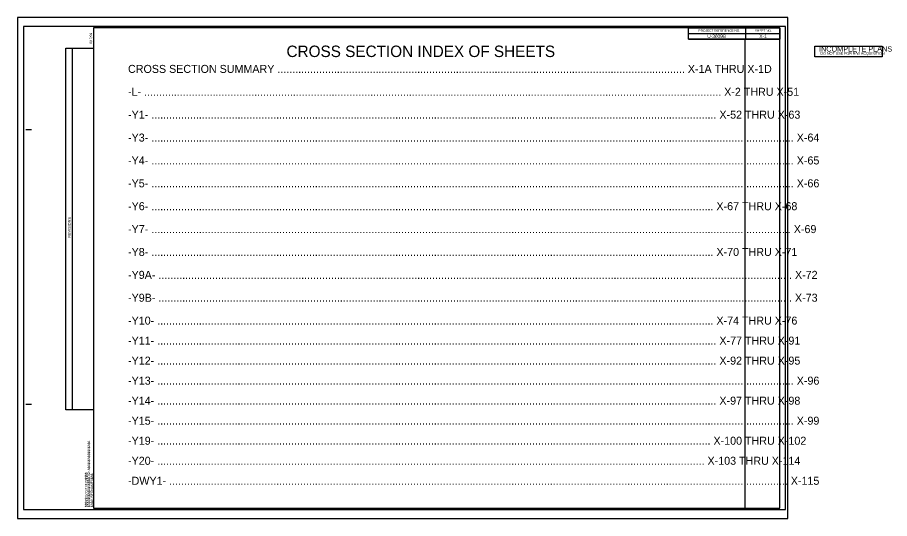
# Model space of a CAD drawing. Extents: x 2087843 to 2088605, y 507344 to 507782.
import ezdxf

# ---------------------------------------------------------------- set-up
doc = ezdxf.new("R2010")
doc.units = 0
for name, color, linetype in [('Prop XS Label Text', 7, 'Continuous'), ('Scratch_Level_1', 7, 'Continuous'), ('Sheet Block Revision CELL', 7, 'Continuous'), ('Sheet Data Field CELL', 7, 'Continuous'), ('Sheet Plan CELL', 7, 'Continuous'), ('Sheet Plot Border Inside CELL', 7, 'Continuous'), ('Sheet Plot Border Outside CELL', 7, 'Continuous'), ('Sheet Sticker Incomplete CELL', 7, 'Continuous')]:
    doc.layers.add(name, color=color, linetype=linetype)

msp = doc.modelspace()

# ---------------------------------------------------------------- linework, layer by layer
at = {"layer": 'Scratch_Level_1'}
msp.add_line((2088478.81, 507763.47), (2088478.81, 507353.5), dxfattribs=at)
at = {"layer": 'Sheet Block Revision CELL'}
msp.add_line((2087890.94, 507439.5), (2087890.94, 507755.75), dxfattribs=at)
msp.add_lwpolyline([(2087885.12, 507439.49), (2087885.12, 507755.75), (2087909.34, 507755.76), (2087909.34, 507439.5)], close=True, dxfattribs=at)
at = {"layer": 'Sheet Plan CELL'}
for p, q in [((2087909.33, 507773.5), (2087909.33, 507773.5)), ((2088479.32, 507773.47), (2088479.34, 507763.47)), ((2088429.31, 507768.48), (2088509.33, 507768.48)), ((2088429.32, 507763.47), (2088509.33, 507763.48)), ((2088429.32, 507763.47), (2088509.33, 507763.48)), ((2087849.93, 507684.49), (2087854.94, 507684.5)), ((2087849.94, 507444.49), (2087854.94, 507444.49)), ((2087909.33, 507353.5), (2087909.33, 507353.5))]:
    msp.add_line(p, q, dxfattribs=at)
for points in [[(2088509.35, 507773.5), (2087909.33, 507773.5), (2087909.33, 507353.5), (2088509.34, 507353.5)], [(2088429.32, 507773.5), (2088509.35, 507773.5), (2088509.33, 507763.48), (2088429.32, 507763.47)]]:
    msp.add_lwpolyline(points, close=True, dxfattribs=at)
at = {"layer": 'Sheet Plot Border Inside CELL'}
msp.add_lwpolyline([(2087847.94, 507352.49), (2088514.33, 507352.5), (2088514.34, 507774.49), (2087847.94, 507774.49)], close=True, dxfattribs=at)
at = {"layer": 'Sheet Plot Border Outside CELL'}
msp.add_lwpolyline([(2087842.74, 507344.49), (2088516.14, 507344.49), (2088516.14, 507782.49), (2087842.74, 507782.49)], close=True, dxfattribs=at)
at = {"layer": 'Sheet Sticker Incomplete CELL'}
msp.add_lwpolyline([(2088539.94, 507747.97), (2088539.94, 507757.37), (2088598.74, 507757.37), (2088598.74, 507747.97)], close=True, dxfattribs=at)

# ---------------------------------------------------------------- texts
at = {"layer": 'Prop XS Label Text'}
for s, height, p in [('CROSS SECTION INDEX OF SHEETS', 10, (2088077.99, 507747.88)), ('CROSS SECTION SUMMARY ......................................................................................................................................... X-1A THRU X-1D', 7, (2087939.44, 507734.01)), ('-L- .................................................................................................................................................................................................. X-2 THRU X-51', 7, (2087939.44, 507714.01)), ('-Y1- .............................................................................................................................................................................................. X-52 THRU X-63', 7, (2087939.44, 507694.01)), ('-Y3- ........................................................................................................................................................................................................................ X-64', 7, (2087939.44, 507674.01)), ('-Y4- ........................................................................................................................................................................................................................ X-65', 7, (2087939.44, 507654.01)), ('-Y5- ........................................................................................................................................................................................................................ X-66', 7, (2087939.44, 507634.01)), ('-Y6- ............................................................................................................................................................................................. X-67 THRU X-68', 7, (2087939.44, 507614.01)), ('-Y7- ....................................................................................................................................................................................................................... X-69', 7, (2087939.44, 507594.01)), ('-Y8- ............................................................................................................................................................................................. X-70 THRU X-71', 7, (2087939.44, 507574.01)), ('-Y9A- ..................................................................................................................................................................................................................... X-72', 7, (2087939.44, 507554.01)), ('-Y9B- ..................................................................................................................................................................................................................... X-73', 7, (2087939.44, 507534.01)), ('-Y10- ........................................................................................................................................................................................... X-74 THRU X-76', 7, (2087939.44, 507514.01)), ('-Y11- ............................................................................................................................................................................................ X-77 THRU X-91', 7, (2087939.44, 507496.51)), ('-Y12- ............................................................................................................................................................................................ X-92 THRU X-95', 7, (2087939.44, 507479.01)), ('-Y13- ...................................................................................................................................................................................................................... X-96', 7, (2087939.44, 507461.51)), ('-Y14- ............................................................................................................................................................................................ X-97 THRU X-98', 7, (2087939.44, 507444.01)), ('-Y15- ...................................................................................................................................................................................................................... X-99', 7, (2087939.44, 507426.51)), ('-Y19- .......................................................................................................................................................................................... X-100 THRU X-102', 7, (2087939.44, 507409.01)), ('-Y20- ........................................................................................................................................................................................ X-103 THRU X-114', 7, (2087939.44, 507391.51)), ('-DWY1- ................................................................................................................................................................................................................ X-115', 7, (2087939.44, 507374.01))]:
    msp.add_text(s, height=height, dxfattribs=at).set_placement(p)
at = {"layer": 'Sheet Block Revision CELL'}
msp.add_text('REVISIONS', height=2.4, rotation=90, dxfattribs=at).set_placement((2087889.32, 507589.96))
at = {"layer": 'Sheet Data Field CELL'}
for s, p in [('U-3609B', (2088445.83, 507764.57)), ('X-1', (2088491.39, 507764.6))]:
    msp.add_text(s, height=3, rotation=0, dxfattribs=at).set_placement(p)
at = {"layer": 'Sheet Plan CELL'}
for s, height, rotation, p in [('PROJECT REFERENCE NO.', 2, 0, (2088438.2, 507770.01)), ('SHEET NO.', 2, 0, (2088487.46, 507769.97)), ('8/17/99', 2.1, 90, (2087908.04, 507759.41)), ('$$$$$$$$$$$$$$$$DGN$$$$$$$$$$$$$$$$', 2.1, 90, (2087906.28, 507354.44)), ('$$$$$$SYSTIME$$$$$', 2.1, 90, (2087903.85, 507354.43)), ('$$$$USERNAME$$$$', 2.1, 90, (2087908.9, 507354.45))]:
    msp.add_text(s, height=height, rotation=rotation, dxfattribs=at).set_placement(p)
at = {"layer": 'Sheet Sticker Incomplete CELL'}
for s, height, p in [('INCOMPLETE PLANS', 4.608, (2088543.52, 507752.65)), ('DO NOT USE FOR R/W ACQUISITION', 2.304, (2088544.82, 507749.87))]:
    msp.add_text(s, height=height, dxfattribs=at).set_placement(p)

doc.saveas('drawing.dxf')
